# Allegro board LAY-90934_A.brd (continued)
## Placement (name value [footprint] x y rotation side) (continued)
R358  $  [0402_CC]  139.45 16.51 270 top
R359  $  [0402_CC]  34.67 16 0 top
R360  $  [0402_CC]  44.2 15.75 0 top
R361  $  [1206_CC]  79.25 15.62 270 top
R362  $  [0402_CC]  34.67 14.99 0 top
R363  $  [0402_CC]  67.94 14.35 180 top
R364  $  [0402_CC]  34.67 13.97 0 top
R365  $  [1206_CC]  52.07 13.34 180 top
R366  $  [0402_CC]  67.94 13.34 180 top
R367  $  [0402_CC]  20.7 12.95 90 top
R368  $  [0402_CC]  34.67 12.95 0 top
R369  $  [0402_CC]  29.97 11.94 270 top
R370  $  [0402_CC]  30.99 11.94 270 top
R371  $  [0402_CC]  2.29 11.81 270 top
R372  $  [0402_CC]  79.63 11.3 270 top
R373  $  [0402_CC]  64.77 10.54 90 top
R374  $  [0402_CC]  65.79 10.54 90 top
R375  $  [0402_CC]  70.1 10.54 270 top
R376  $  [0402_CC]  71.12 10.54 270 top
R377  $  [RC0402_25]  13.08 9.27 90 top
R378  $  [RC0402_25]  19.81 9.27 90 top
R379  $  [0402_CC]  1.52 6.48 90 top
R380  $  [0402_CC]  68.2 6.22 90 top
R381  $  [0402_CC]  75.18 6.22 90 top
R382  $  [0402_CC]  64.77 5.08 270 top
R383  $  [0402_CC]  75.18 4.57 90 top
R384  $  [0402_CC]  79.38 4.32 270 top
R385  $  [0402_CC]  68.2 3.81 270 top
R386  10K  [0402_CC]  135.64 2.92 90 top
R387  10K  [0402_CC]  136.91 2.92 90 top
R388  $  [RC0402_25]  77.98 80.65 270 bottom
R389  $  [RC0402_25]  75.18 80.65 270 bottom
R390  $  [RC0402_25]  72.39 80.65 270 bottom
R391  $  [0402_CC]  79.63 75.31 90 bottom
R392  10K  [0402_CC]  78.61 75.31 270 bottom
R393  $  [0402_CC]  76.83 75.31 90 bottom
R394  10K  [0402_CC]  75.82 75.31 270 bottom
R395  $  [0402_CC]  73.91 75.31 90 bottom
R396  10K  [0402_CC]  72.9 75.31 270 bottom
R397  $  [0402_CC]  49.02 73.53 90 bottom
R398  $  [0402_CC]  48.01 73.53 90 bottom
R399  $  [0402_CC]  46.99 73.53 90 bottom
R400  $  [0402_CC]  58.42 73.03 90 bottom
R401  $  [0402_CC]  57.4 73.03 90 bottom
R402  $  [0402_CC]  56.39 73.03 90 bottom
R403  $  [0402_CC]  55.37 73.03 90 bottom
R404  $  [0402_CC]  115.19 72.52 0 bottom
R405  4.7K  [0402_CC]  103.89 68.58 90 bottom
R406  $  [RC0402_25]  102.87 68.58 270 bottom
R407  $  [RC0402_25]  101.85 68.58 270 bottom
R408  4.7K  [0402_CC]  100.84 68.58 90 bottom
R409  $  [0402_CC]  58.42 67.06 90 bottom
R410  $  [0402_CC]  57.4 67.06 90 bottom
R411  $  [0402_CC]  56.39 67.06 270 bottom
R412  $  [0402_CC]  55.37 67.06 270 bottom
R413  10K  [0402_CC]  51.56 66.42 90 bottom
R414  10K  [0402_CC]  50.55 66.42 90 bottom
R415  10K  [0402_CC]  52.58 66.42 90 bottom
R416  $  [0402_CC]  49.28 66.42 270 bottom
R417  $  [0402_CC]  48.26 66.42 270 bottom
R418  $  [0402_CC]  47.24 66.42 270 bottom
R419  $  [RC0402_25]  102.87 66.04 90 bottom
R420  $  [RC0402_25]  101.85 66.04 90 bottom
R421  $  [0402_CC]  67.82 65.53 90 bottom
R422  $  [0402_CC]  66.55 65.53 90 bottom
R423  $  [0402_CC]  65.28 65.53 90 bottom
R424  $  [0402_CC]  64.01 65.53 90 bottom
R425  $  [0402_CC]  40.39 64.77 270 bottom
R426  10K  [0402_CC]  39.37 64.77 90 bottom
R427  $  [RC0402_25]  60.32 64.52 0 bottom
R428  $  [RC0402_25]  60.32 63.5 0 bottom
R429  $  [RC0402_25]  60.32 62.48 0 bottom
R430  10K  [0402_CC]  114.05 61.85 90 bottom
R431  $  [RC0402_25]  60.32 61.47 0 bottom
R432  $  [0402_CC]  60.32 60.45 180 bottom
R433  2.2K  [0402_CC]  111.38 60.2 180 bottom
R434  2.2K  [0402_CC]  111.38 58.93 180 bottom
R435  $  [0402_CC]  53.72 49.4 0 bottom
R436  $  [0402_CC]  57.15 49.15 0 bottom
R437  $  [0402_CC]  55.75 48.77 270 bottom
R438  $  [0402_CC]  59.18 41.15 270 bottom
R439  $  [0402_CC]  48.39 38.99 180 bottom
R440  $  [0402_CC]  41.66 36.7 180 bottom
R441  $  [RC0402_25]  35.94 36.7 180 bottom
R442  $  [0402_CC]  77.98 36.58 180 bottom
R443  $  [RC0402_25]  96.52 36.45 270 bottom
R444  4.7K  [RC0402_25]  95.5 36.45 270 bottom
R445  4.7K  [RC0402_25]  94.49 36.45 270 bottom
R446  4.7K  [RC0402_25]  93.47 36.45 270 bottom
R447  4.7K  [RC0402_25]  92.46 36.45 270 bottom
R448  $  [0402_CC]  41.66 35.69 180 bottom
R449  $  [0201_CC]  32.77 35.18 180 bottom
R450  $  [0402_CC]  41.66 34.67 180 bottom
R451  $  [0201_CC]  32.77 34.42 180 bottom
R452  4.7K  [RC0402_25]  96.52 33.91 270 bottom
R453  $  [RC0402_25]  95.5 33.91 270 bottom
R454  $  [RC0402_25]  94.49 33.91 270 bottom
R455  $  [RC0402_25]  93.47 33.91 270 bottom
R456  $  [RC0402_25]  92.46 33.91 270 bottom
R457  $  [RC0402_25]  91.44 33.91 270 bottom
R458  0  [0402_CC]  90.42 33.91 270 bottom
R459  $  [0402_CC]  41.66 33.66 180 bottom
R460  $  [0402_CC]  41.66 32.64 180 bottom
R461  $  [0402_CC]  41.66 31.62 180 bottom
R462  $  [0603_CC]  95.38 31.5 90 bottom
R463  $  [0402_CC]  33.27 31.24 270 bottom
R464  10K  [0402_CC]  32.26 31.24 270 bottom
R465  $  [0402_CC]  124.97 31.12 0 bottom
R466  $  [0402_CC]  41.66 30.61 180 bottom
R467  $  [0402_CC]  124.97 30.1 0 bottom
R468  $  [0603_CC]  87.12 30.1 270 bottom
R469  $  [0402_CC]  41.66 29.59 180 bottom
R470  $  [0402_CC]  34.92 29.59 180 bottom
R471  1.5K  [0402_CC]  97.92 29.08 180 bottom
R472  0  [0402_CC]  47.12 22.48 270 bottom
R473  $  [0402_CC]  46.74 20.7 0 bottom
R474  $  [RC0402_25]  45.34 20.19 270 bottom
R475  $  [0402_CC]  21.97 16.38 90 bottom
R476  1K  [0402_CC]  53.09 7.11 0 bottom
R477  $  [0402_CC]  53.09 6.1 0 bottom
R478  $  [0402_CC]  53.09 4.83 180 bottom
R479  $  [RC0805_OV]  54.99 3.3 180 bottom
R480  0  [0402_CC]  125.73 16.51 90 top
R481  $  [0402_CC]  33.27 31.24 270 top
S1  $  [SW_2P8X5P7_SM]  34.29 67.18 270 top
SW1  $  [SW4_SKRP]  14.73 80.77 0 top
SW2  $  [SW4_SKRP]  25.53 80.77 0 top
SW3  $  [SW_CHS_04_A]  65.91 68.2 90 top
SW4  $  [SW_CHS_04_A]  133.73 67.18 0 top
SW5  $  [SW6_DPDT_M096H_TH]  73.41 1.65 180 top
TP1  TP_35MIL  [TESTPOINT_35MIL]  78.11 83.19 0 top
TP2  TP_35MIL  [TESTPOINT_35MIL]  8.08 82.07 0 top
TP3  -  [TPAD_050]  39.32 33.02 0 top
TP4  TP_35MIL  [TESTPOINT_35MIL]  25.27 78.11 0 top
TP5  TP_35MIL  [TESTPOINT_35MIL]  29.08 78.11 0 top
TP6  TP_35MIL  [TESTPOINT_35MIL]  11.18 76.96 0 top
TP7  -  [TPAD_020]  19.05 74.8 90 top
TP8  -  [TPAD_020]  20.32 74.8 90 top
TP9  -  [TPAD_020]  17.78 73.28 90 top
TP10  -  [TPAD_020]  19.05 73.28 90 top
TP11  -  [TPAD_020]  20.32 73.28 90 top
TP12  -  [TPAD_050]  82.68 73.28 0 top
TP13  -  [TPAD_020]  43.18 73.15 0 top
TP14  -  [TPAD_020]  101.73 71.88 0 top
TP15  -  [TPAD_020]  47.5 69.09 0 top
TP16  TP_35MIL  [TESTPOINT_35MIL]  101.85 68.96 0 top
TP17  TP_35MIL  [TESTPOINT_35MIL]  103.25 68.96 0 top
TP18  -  [TPAD_020]  47.5 67.82 0 top
TP19  -  [TPAD_020]  86.49 68.2 0 top
TP20  -  [TPAD_020]  87.76 68.2 0 top
TP21  -  [TPAD_020]  90.55 68.2 0 top
TP22  -  [TPAD_020]  92.46 68.2 0 top
TP23  -  [TPAD_020]  93.73 68.2 0 top
TP24  -  [TPAD_020]  20.7 67.18 90 top
TP25  -  [TPAD_020]  20.68 65.91 90 top
TP26  -  [TPAD_020]  85.22 64.9 0 top
TP27  -  [TPAD_020]  86.49 64.9 0 top
TP28  -  [TPAD_050]  14.73 59.28 0 top
TP29  TP_35MIL  [TESTPOINT_35MIL]  69.09 62.87 90 top
TP30  -  [TPAD_015]  91.31 62.23 0 top
TP31  -  [TPAD_015]  95.12 62.23 0 top
TP32  TP_35MIL  [TESTPOINT_35MIL]  69.09 61.47 90 top
TP33  TP_35MIL  [TESTPOINT_35MIL]  64.64 61.21 90 top
TP34  TP_35MIL  [TESTPOINT_35MIL]  66.04 61.21 90 top
TP35  -  [TPAD_015]  79.5 58.55 0 top
TP36  -  [TPAD_015]  82.8 57.17 0 top
TP37  TP_35MIL  [TESTPOINT_35MIL]  16 56.9 270 top
TP38  TP_35MIL  [TESTPOINT_35MIL]  17.4 56.9 270 top
TP39  -  [TPAD_015]  84.84 55.63 0 top
TP40  -  [TPAD_050]  108.97 55.63 0 top
TP41  TP_35MIL  [TESTPOINT_35MIL]  49.15 55.37 0 top
TP42  TP_35MIL  [TESTPOINT_35MIL]  50.55 55.12 0 top
TP43  -  [TPAD_015]  85.72 55.12 0 top
TP44  -  [TPAD_020]  125.6 55.12 0 top
TP45  -  [TPAD_015]  84.84 54.99 0 top
TP46  -  [TPAD_020]  13.84 54.61 270 top
TP47  -  [TPAD_015]  85.06 54.36 0 top
TP48  -  [TPAD_015]  85.09 53.72 0 top
TP49  -  [TPAD_015]  85.47 53.09 0 top
TP50  -  [TPAD_020]  125.6 52.83 0 top
TP51  -  [TPAD_015]  84.84 52.71 0 top
TP52  TP_35MIL  [TESTPOINT_35MIL]  57.4 52.45 90 top
TP53  TP_35MIL  [TESTPOINT_35MIL]  62.48 52.45 90 top
TP54  -  [TPAD_015]  85.47 52.07 0 top
TP55  -  [TPAD_020]  125.73 51.69 0 top
TP56  TP_35MIL  [TESTPOINT_35MIL]  37.08 51.44 180 top
TP57  TP_35MIL  [TESTPOINT_35MIL]  40.77 51.44 0 top
TP58  TP_35MIL  [TESTPOINT_35MIL]  42.29 51.44 0 top
TP59  TP_35MIL  [TESTPOINT_35MIL]  44.58 51.44 180 top
TP60  -  [TPAD_015]  85.6 51.44 0 top
TP61  TP_35MIL  [TESTPOINT_35MIL]  122.43 51.44 90 top
TP62  TP_35MIL  [TESTPOINT_35MIL]  123.83 51.44 90 top
TP63  TP_35MIL  [TESTPOINT_35MIL]  62.48 50.93 90 top
TP64  -  [TPAD_015]  85.6 50.8 0 top
TP65  -  [TPAD_015]  84.84 50.67 0 top
TP66  TP_35MIL  [TESTPOINT_35MIL]  45.21 50.17 180 top
TP67  -  [TPAD_015]  85.09 49.91 0 top
TP68  TP_35MIL  [TESTPOINT_35MIL]  33.4 49.66 180 top
TP69  TP_35MIL  [TESTPOINT_35MIL]  34.92 49.66 180 top
TP70  TP_35MIL  [TESTPOINT_35MIL]  37.08 49.66 180 top
TP71  -  [TPAD_020]  54.15 48.51 90 top
TP72  -  [TPAD_015]  84.96 49.15 0 top
TP73  -  [TPAD_015]  84.84 47.31 0 top
TP74  TP_35MIL  [TESTPOINT_35MIL]  58.55 47.12 180 top
TP75  -  [TPAD_050]  60.71 47.12 0 top
TP76  TP_35MIL  [TESTPOINT_35MIL]  37.85 46.99 180 top
TP77  -  [TPAD_015]  84.96 46.61 0 top
TP78  -  [TPAD_015]  81.51 48.11 180 bottom
TP79  -  [TPAD_015]  80.86 48.11 180 bottom
TP80  TP_35MIL  [TESTPOINT_35MIL]  35.81 45.21 0 top
TP81  TP_35MIL  [TESTPOINT_35MIL]  37.85 45.21 0 top
TP82  TP_35MIL  [TESTPOINT_35MIL]  129.03 44.96 0 top
TP83  -  [TPAD_020]  91.82 44.58 0 top
TP84  -  [TPAD_020]  90.55 44.32 0 top
TP85  -  [TPAD_020]  58.42 44.2 270 top
TP86  -  [TPAD_020]  86.23 43.18 0 top
TP87  -  [TPAD_020]  87.5 43.18 0 top
TP88  -  [TPAD_020]  88.77 43.18 0 top
TP89  -  [TPAD_020]  91.06 43.18 0 top
TP90  -  [TPAD_020]  104.77 42.93 0 top
TP91  TP_35MIL  [TESTPOINT_35MIL]  35.81 41.66 90 top
TP92  TP_35MIL  [TESTPOINT_35MIL]  37.85 41.66 180 top
TP93  -  [TPAD_020]  97.03 42.8 0 top
TP94  TP_35MIL  [TESTPOINT_35MIL]  138.81 41.66 0 top
TP95  -  [TPAD_020]  86.23 41.28 0 top
TP96  -  [TPAD_020]  87.5 41.28 0 top
TP97  -  [TPAD_020]  7.24 40.77 0 top
TP98  TP_35MIL  [TESTPOINT_35MIL]  121.28 40.51 90 top
TP99  -  [TPAD_020]  14.22 40.39 0 top
TP100  -  [TPAD_020]  15.49 40.39 0 top
TP101  -  [TPAD_020]  16.76 40.39 0 top
TP102  TP_35MIL  [TESTPOINT_35MIL]  56.26 40.39 180 top
TP103  -  [TPAD_015]  104.77 40.39 0 top
TP104  -  [TPAD_020]  89.92 40.26 0 top
TP105  TP_35MIL  [TESTPOINT_35MIL]  39.62 40.01 180 top
TP106  TP_35MIL  [TESTPOINT_35MIL]  64.52 39.88 0 top
TP107  -  [TPAD_020]  104.77 39.12 0 top
TP108  TP_35MIL  [TESTPOINT_35MIL]  35.81 38.1 0 top
TP109  TP_35MIL  [TESTPOINT_35MIL]  37.97 38.1 0 top
TP110  -  [TPAD_020]  104.77 37.85 0 top
TP111  TP_35MIL  [TESTPOINT_35MIL]  49.02 37.47 180 top
TP112  TP_35MIL  [TESTPOINT_35MIL]  51.43 37.47 180 top
TP113  TP_35MIL  [TESTPOINT_35MIL]  52.83 37.47 180 top
TP114  -  [TPAD_020]  18.67 36.83 0 top
TP115  TP_35MIL  [TESTPOINT_35MIL]  3.17 36.7 0 top
TP116  TP_35MIL  [TESTPOINT_35MIL]  60.58 36.07 0 top
TP117  TP_35MIL  [TESTPOINT_35MIL]  62.86 36.07 0 top
TP118  TP_35MIL  [TESTPOINT_35MIL]  45.72 35.81 180 top
TP119  TP_35MIL  [TESTPOINT_35MIL]  47.62 35.81 180 top
TP120  TP_35MIL  [TESTPOINT_35MIL]  49.15 35.81 180 top
TP121  TP_35MIL  [TESTPOINT_35MIL]  54.23 35.81 270 top
TP122  -  [TPAD_020]  18.67 35.56 0 top
TP123  -  [TPAD_020]  3.17 35.05 0 top
TP124  TP_35MIL  [TESTPOINT_35MIL]  26.92 34.54 90 top
TP126  TP_35MIL  [TESTPOINT_35MIL]  54.23 34.29 270 top
TP127  TP_35MIL  [TESTPOINT_35MIL]  49.15 34.16 180 top
TP128  -  [TPAD_050]  142.11 33.78 0 top
TP130  TP_35MIL  [TESTPOINT_35MIL]  30.1 32.13 0 top
TP131  TP_35MIL  [TESTPOINT_35MIL]  64.9 32.13 0 top
TP132  TP_35MIL  [TESTPOINT_35MIL]  66.93 32.13 0 top
TP133  -  [TPAD_020]  95.12 32 0 top
TP134  -  [TPAD_020]  96.39 32 0 top
TP135  TP_35MIL  [TESTPOINT_35MIL]  97.16 30.86 0 top
TP136  -  [TPAD_020]  3.17 30.73 0 top
TP137  -  [TPAD_020]  95.12 30.73 0 top
TP138  -  [TPAD_020]  86.87 30.48 0 top
TP139  TP_35MIL  [TESTPOINT_35MIL]  30.1 30.1 0 top
TP140  -  [TPAD_020]  97.16 29.08 0 top
TP141  TP_35MIL  [TESTPOINT_35MIL]  133.1 29.08 0 top
TP142  -  [TPAD_020]  142.11 28.7 90 top
TP143  -  [TPAD_020]  97.79 28.07 0 top
TP144  -  [TPAD_020]  97.79 26.8 0 top
TP145  TP_35MIL  [TESTPOINT_35MIL]  24.51 25.91 90 top
TP146  -  [TPAD_020]  101.35 25.65 0 top
TP147  -  [TPAD_020]  2.92 24.77 270 top
TP148  -  [TPAD_020]  101.35 24.38 0 top
TP149  -  [TPAD_020]  115.25 24.26 0 top
TP150  -  [TPAD_020]  115.25 22.99 0 top
TP151  -  [TPAD_020]  45.21 18.03 90 top
TP152  -  [TPAD_050]  66.07 17.25 0 top
TP153  -  [TPAD_020]  67.94 17.15 0 top
TP154  -  [TPAD_020]  33.66 17.02 0 top
TP156  -  [TPAD_020]  67.94 15.49 0 top
TP157  -  [TPAD_020]  74.55 15.49 0 top
TP158  -  [TPAD_020]  2.92 15.37 270 top
TP159  -  [TPAD_020]  4.19 15.37 270 top
TP160  TP_35MIL  [TESTPOINT_35MIL]  5.84 15.37 0 top
TP161  TP_35MIL  [TESTPOINT_35MIL]  8 15.37 0 top
TP162  TP_35MIL  [TESTPOINT_35MIL]  104.01 14.48 0 top
TP163  TP_35MIL  [TESTPOINT_35MIL]  112.9 14.48 0 top
TP164  TP_35MIL  [TESTPOINT_35MIL]  66.04 14.35 0 top
TP165  -  [TPAD_020]  74.55 14.22 0 top
TP166  -  [TPAD_020]  28.19 13.97 270 top
TP167  -  [TPAD_050]  15.75 12.95 0 top
TP168  TP_35MIL  [TESTPOINT_35MIL]  66.04 12.95 0 top
TP169  -  [TPAD_020]  67.31 12.19 0 top
TP170  -  [TPAD_020]  68.71 12.19 0 top
TP171  -  [TPAD_020]  33.66 11.94 0 top
TP172  -  [TPAD_020]  74.17 10.54 0 top
TP173  -  [TPAD_020]  28.57 9.27 0 top
TP174  -  [TPAD_020]  32.38 9.27 0 top
TP175  -  [TPAD_020]  48.26 8.64 0 top
TP176  -  [TPAD_020]  49.53 8.64 0 top
TP177  -  [TPAD_020]  125.6 4.45 0 top
TP178  -  [TPAD_020]  132.21 4.45 0 top
TP179  -  [TPAD_020]  133.48 4.45 0 top
TP180  -  [TPAD_020]  135.64 4.45 0 top
TP181  -  [TPAD_020]  136.91 4.45 0 top
TP182  -  [TPAD_020]  139.45 4.45 0 top
TP183  -  [TPAD_020]  138.18 2.92 0 top
TP184  -  [TPAD_020]  139.45 2.92 0 top
TP185  -  [TPAD_050]  57.78 2.79 270 top
TP186  TP_35MIL  [TESTPOINT_35MIL]  59.36 74.12 90 top
TP187  TP_35MIL  [TESTPOINT_35MIL]  59.36 72.39 90 top
TP188  -  [TPAD_050]  57.78 6.35 0 top
TVS1  $  [DIODE2_SOD523]  110.74 14.48 0 top
TVS2  $  [DIODE2_SOD523]  106.17 14.48 180 top
TVS3  $  [DIODE2_SOD523]  11.94 9.4 270 top
U1  $  [PBGA208_0P5_9X9MM_SM]  94.23 52.83 0 top
U2  $  [BGA200_0P65X0P8_10P1X14P6]  76.96 51.31 270 top
U3  $  [SC70-5]  8 79.88 270 top
U4  $  [LGA8_3P1X4P1MM_SPK0641]  4.06 78.87 0 top
U5  $  [LGA8_3P1X4P1MM_SPK0641]  80.64 78.87 0 top
U6  $  [WLCSP6_0P5_0P89X1P39]  87.88 75.95 180 top
U7  $  [SOT-23-5]  8 74.3 270 top
U8  $  [SO8_1P27_4X5]  27.18 71.63 270 top
U9  TMUX1574RSVR  [PQFN16_0P4_2P65X1P85]  116.08 71.37 0 top
U10  $  [PQFN16_0P4_2P65X1P85]  99.06 70.99 0 top
U11  $  [WLCSP6_0P4_0P84X1P18]  102.23 70.49 270 top
U12  $  [SO16_0P5_3P5X4P5_MM]  17.53 70.23 90 top
U13  $  [QFN24_4X4_EP2P25MM]  43.94 69.85 0 top
U14  74AUP1G126GM  [UDFN6_1X1P5MM]  40 64.77 270 top
U15  $  [UQFN32_0P5_5X5_EP3X3]  116.71 62.48 90 top
U16  $  [QFN16_0P65_4X4_A]  46.23 58.29 0 top
U17  $  [QFN16_0P65_4X4_A]  28.57 54.99 0 top
U18  $  [HWSON8_0P5_3P1X2P1]  15.75 52.07 270 top
U19  $  [WSON10_0P5_2P1X3P1]  56.52 49.66 0 top
U20  $  [WSON8_1P27_8X6MM_EP136X171]  121.92 46.1 90 top
U21  $  [QFN16_0P65_4X4_A]  20.07 45.34 0 top
U22  $  [SOT753_5P_1P7X3P1MM]  136.27 44.45 0 top
U23  $  [QFN40_0P4_5X5_EP146X146]  48.39 44.07 180 top
U24  $  [WSON10_0P5_2P1X3P1]  59.69 41.78 270 top
U25  $  [FBGA153_0P5_11P5X13]  111.51 41.28 0 top
U26  $  [WLCSP4_0P5_0P99X0P99]  136.27 39.37 270 top
U27  $  [PQFN16_0P4_2P65X1P85]  81.28 35.43 0 top
U28  $  [LQFP64_0P5_10X10]  11.05 32.77 90 top
U29  TMUX1574RSVR  [PQFN16_0P4_2P65X1P85]  112.52 32.13 90 top
U30  TMUX1574RSVR  [PQFN16_0P4_2P65X1P85]  116.97 32.13 90 top
U31  $  [PQFN16_0P4_2P65X1P85]  127.38 32.13 90 top
U32  $  [QFN12_0P5_2X3MM_EP]  139.95 30.23 0 top
U33  $  [SOT23-5]  23.5 30.1 0 top
U34  $  [SC70-5]  72.64 29.97 0 top
U35  $  [QFN40_0P4_5X5MM]  91.06 29.34 90 top
U36  $  [SOT-23-5]  30.99 24 270 top
U37  $  [XSON10_0P5_1P1X2P6MM]  88.52 22.35 90 top
U38  $  [XSON10_0P5_1P1X2P6MM]  93.6 22.35 90 top
U39  $  [QFN0505-32B_0P5]  48.01 22.1 90 top
U40  $  [TSSOP16]  108.46 21.59 180 top
U41  $  [UQFN12_1P7X2MM]  122.43 21.21 90 top
U42  $  [SOT23-6]  4.06 20.45 180 top
U43  $  [XQFN12_0P4_1P8X2P1]  129.79 19.69 90 top
U44  $  [XQFN12_0P4_1P8X2P1]  138.43 19.69 90 top
U45  $  [WLCSP15_0P5_1P57X2P59]  66.29 19.43 270 top
U46  $  [SOT-23]  26.42 17.4 90 top
U47  $  [WLCSP42_0P4_2P94X2P54_SMDP]  19.3 16.26 180 top
U48  $  [HX2QFN16_0P4_2P7X2P7]  31.5 15.24 90 top
U49  $  [HX2QFN16_0P4_2P7X2P7]  71.25 13.84 270 top
U50  $  [SOT23-5]  8.13 12.6 90 top
U51  $  [WLCSP12_0P4_1P3X1P7MM_SMDP]  27.69 11.94 90 top
U52  $  [WLCSP12_0P4_1P3X1P7MM_SMDP]  75.69 10.29 180 top
U53  $  [SC70-5]  8.13 9.4 270 top
U54  $  [WLCSP5_0P4_0P82X1P22]  14.48 9.27 180 top
U55  $  [WLCSP5_0P4_0P82X1P22]  29.85 9.27 180 top
U56  $  [LGA8_3P1X4P1MM_SPK0641]  4.06 8 0 top
U57  $  [LGA8_3P1X4P1MM_SPK0641]  80.64 8 0 top
U58  $  [DFN2020_0P5_SQ2]  54.99 5.97 270 top
U59  TMUX1574RSVR  [PQFN16_0P4_2P65X1P85]  128.78 70.61 0 bottom
U60  $  [XQFN16_0P4_2P7X1P9]  57.66 69.98 90 bottom
U61  $  [SSOP8_DCU]  51.31 69.98 180 bottom
U62  $  [SSOP8_DCU]  48.26 69.98 0 bottom
U63  $  [XQFN16_0P4_2P7X1P9]  63.25 62.74 180 bottom
U64  $  [QFN16_0P65_4X4_A]  36.83 33.15 0 bottom
U65  $  [XQFN12_0P4_1P8X2P1]  20.96 29.97 0 bottom
U66  $  [SC70-5]  80.64 83.19 270 top
U67  $  [WLCSP6_0P5_0P89X1P39]  87.63 82.04 180 top
U68  $  [SC70-5]  132.21 47.75 90 bottom
X1  $  [XTAL_4_3P3X2P6MM]  9.02 22.1 0 top
Y1  $  [XTLOSC4_3P2X2P5MM_SM]  95.76 65.79 180 top
Y2  $  [XTL4_2P5X2MM_SM]  83.31 30.61 0 top

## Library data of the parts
BH1-BH5 = MOUNT_HOLE
BT1 = BATTERY_SKT_3V
C1-C9 C11-C13 C15-C28 C30-C33 C36 C38-C49 C51 C53-C63 C66-C70 C72-C93 C96-C111 C113 C115-C119 C122-C125 C127 C129-C133 C135-C140 C142-C146 C149-C153 C155-C176 C178-C196 C198 C200-C223 C225 C226 C228 C229 C231 C232 C234 C235 C237-C242 C244-C261 C263-C268 C270-C275 C277-C279 C281-C283 C286-C288 C290-C296 C298 C299 C301-C318 = CAP_NP
C10 C14 C29 C34 C35 C37 C50 C52 C64 C65 C71 C114 C120 C148 C177 C197 C199 C224 C227 C230 C233 C236 C243 C269 C276 C280 C284 C285 C289 C297 C300 = CAP_NP: tolerance: 10%
C94 C95 C112 C121 C262 = CAP_NP: room: RGMII_PHY
C128 C134 = CAP_NP: tolerance: 5%; room: RGMII_PHY
C141 = CAP_POL
C154 = MOT_CAP
D1 = LED_GPLY6900
D2 = ESD_DIODE_2LINE
D3 D18-D20 D22-D25 D30 = DIODE_SCHTKY
D5 D15-D17 D26-D28 = LED
D6 D7 D9 D11-D13 = DIODE_BIDIR
D10 D14 TVS1-TVS3 = DIODE_TVS_BIDIR
D29 = ZDIODE
F1 F2 = FUSE
GND1 GND2 GND7 GND17 GND26 GND27 TP1 TP2 TP4-TP6 TP16 TP17 TP29 TP32-TP34 TP37 TP38 TP41 TP42 TP52 TP53 TP56-TP59 TP61-TP63 TP66 TP68-TP70 TP74 TP76 TP80-TP82 TP91 TP92 TP94 TP98 TP102 TP105 TP106 TP108 TP109 TP111-TP113 TP115-TP121 TP124 TP126 TP127 TP130-TP132 TP135 TP139 TP141 TP145 TP160-TP164 TP168 TP186 TP187 = T POINT R: Tolerance: TOLERANCE; User Part Number: 510-75618
GND3-GND6 GND8-GND13 GND15 GND16 GND18-GND21 GND23 GND24 GND28 TP3 TP7-TP15 TP18-TP28 TP30 TP31 TP35 TP36 TP39 TP40 TP43-TP51 TP54 TP55 TP60 TP64 TP65 TP67 TP71-TP73 TP75 TP77-TP79 TP83-TP90 TP93 TP95-TP97 TP99-TP101 TP103 TP104 TP107 TP110 TP114 TP122 TP123 TP128 TP133 TP134 TP136-TP138 TP140 TP142-TP144 TP146-TP154 TP156-TP159 TP165-TP167 TP169-TP185 TP188 = TESTLOOP
GND14 GND22 GND25 = TestLoop
J1 = CONN_HDR_3X2
J2 = CONN_HDR_4X1
J3 J5 = CONN_HDR_4X2
J4 = CONN_HDR_20X2
J6 = CONN_MICRO_SDCARD
J7 = CONN_HDR_5X2
J8 = CON_67_FEMALE_RA_B
J9 = RJ45_2 DUAL_LED_10P
J10 = CON_KJ366EYS_AUDIOJACK_6P
J11 J12 = USB24_TYPEC_SH4
J13 = USB6_TYPEC_SH4_1_A
L1 L2 L11 L13-L18 = BEAD_0
L3 L4 = DLW43
L5 L6 L8 L9 = INDUCTOR
L7 = INDUCTOR_FERRITE
L10 = INDUCTOR: tolerance: 20%
L12 = IND
Q1 Q3-Q6 Q8-Q13 = NX3008NBKW_SOT323
QZ1 QZ2 = XTAL
R1-R99 R101-R132 R134-R146 R148-R152 R154-R157 R159-R170 R172-R176 R178-R185 R187-R261 R263-R269 R271-R274 R276-R279 R281-R283 R285-R301 R303-R470 R472-R481 = RES
R133 R147 R153 R171 R177 R186 = RES: signal model: RES_0402_CC_DISCRETE_0.45_MM_470-75394_0_0
R280 = RES: tolerance: 5%
R284 R302 = RES: tolerance: 1%
R471 = RES: room: RGMII_PHY
S1 = SW-SPST_A
SW1 SW2 = SW_TC_SPST_4P
SW3 SW4 = CHS-04TA_SW
SW5 = SW_DPDT_3
U1 = MIMX9122DVXxLAA_BGA208_A
U2 = MT53B768M32D4NQ_200P
U3 U53 U66 = 74LV1T34GWH_TSSOP6
U4 U5 U56 U57 = SPK0641HT4H_8P_A
U6 U67 = NX5P2924DUK_WLCSP6
U7 = NCP161ASN180T1G_A
U8 = TJA1057GT3_8P
U9 U29 U30 U59 = TMUX1574RSVR_A: signal model: TMUX1574RSVR_A_PQFN16_0P4_2P65X1P85_IC_0.55MM_312-82341_TMUX1574RSVR_TMUX1574RSVR
U10 U27 U31 = TMUX1574RSVR_A
U11 = P3T2108_6P
U12 = PCF2131_A
U13 = PCA9655EMTTXG_WQFN24_A
U14 = 74AUP1G126GM
U15 = PCAL6524HE_QFN
U16 U17 U21 U64 = PAC1934_UQFN16_A
U18 = PCT2075 _SON8_EP
U19 U24 = TPS22990NDMLT_WSON10_B
U20 = GD5F1GQ4RCYIG_WSON8
U22 = 74LV1T126GVH
U23 = PF9453AHN_QFN40P
U25 = SDINBDA6_32G_I_VFBGA_153P
U26 = NX3P1108_4P
U28 = FT4232HL_LQFP64
U32 = MP2147GD_QFN_11P
U33 U50 = RT9193-33PB
U34 U68 = 74AUP1G07GW
U35 = RTL8211FDI-40P
U36 = SGM8709YN5G
U37 U38 = DIODE_ESD_4CH_10P_A
U39 = R1273L031A
U40 = WM8524GEDT
U41 = LSF0204_QFN_12P
U42 = 93AA56BT_SOT23-6
U43 U44 = NTB0104GU12_12P
U45 = NX20P5090UK_15P_A
U46 = LM3480IM3
U47 = NX20P3483UK_42P
U48 U49 = PTN5110_QFN16
U51 U52 = NX20P0407_WLCSP12_A
U54 U55 = PESD1USB30_5P
U58 = DML3006LFDS-7_A
U60 U63 = 74AVC4T245GU_XQFN16
U61 = SN74AUP3G04_A
U62 = 74HC3G06DC
U65 = 74AVC4T3144_12P_A
X1 Y1 Y2 = XTAL_13

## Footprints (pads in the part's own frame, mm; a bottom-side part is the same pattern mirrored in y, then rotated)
0201_CC
  rect 0.305x0.305 smd: 1(-0.267,0) 2(0.267,0)
0402_CC
  rect 0.457x0.508 smd: 1(-0.375,0) 2(0.375,0)
0402_CC_NSP
  rect 0.457x0.508 smd: 1(-0.375,0) 2(0.375,0)
0603_CC
  rect 0.711x0.838 smd: 1(-0.65,0) 2(0.65,0)
0805_CC
  rect 0.94x1.346 smd: 1(-0.78,0) 2(0.78,0)
1206_CC
  rect 0.94x1.702 smd: 1(-1.4,0) 2(1.4,0)
1210_CC
  rect 0.94x2.591 smd: 1(-1.4,0) 2(1.4,0)
BATT_6P8MM_SM
  rect 1.778x5.08 smd: 1(-4.701,0) 2(4.701,0)
  rect 3.962x3.962 smd: 3(0,0)
BGA200_0P65X0P8_10P1X14P6
  round 0.279 smd: A1(-4.4,6.825) A2(-3.6,6.825) A3(-2.8,6.825) A4(-2,6.825) A5(-1.2,6.825) A8(1.2,6.825) A9(2,6.825) A10(2.8,6.825) A11(3.6,6.825) A12(4.4,6.825) AA1(-4.4,-6.175) AA2(-3.6,-6.175) AA3(-2.8,-6.175) AA4(-2,-6.175) AA5(-1.2,-6.175) AA8(1.2,-6.175) AA9(2,-6.175) AA10(2.8,-6.175) AA11(3.6,-6.175) AA12(4.4,-6.175) AB1(-4.4,-6.825) AB2(-3.6,-6.825) AB3(-2.8,-6.825) AB4(-2,-6.825) AB5(-1.2,-6.825) AB8(1.2,-6.825) AB9(2,-6.825) AB10(2.8,-6.825) AB11(3.6,-6.825) AB12(4.4,-6.825) B1(-4.4,6.175) B2(-3.6,6.175) B3(-2.8,6.175) B4(-2,6.175) B5(-1.2,6.175) B8(1.2,6.175) B9(2,6.175) B10(2.8,6.175) B11(3.6,6.175) B12(4.4,6.175) C1(-4.4,5.525) C2(-3.6,5.525) C3(-2.8,5.525) C4(-2,5.525) C5(-1.2,5.525) C8(1.2,5.525) C9(2,5.525) C10(2.8,5.525) C11(3.6,5.525) C12(4.4,5.525) D1(-4.4,4.875) D2(-3.6,4.875) D3(-2.8,4.875) D4(-2,4.875) D5(-1.2,4.875) D8(1.2,4.875) D9(2,4.875) D10(2.8,4.875) D11(3.6,4.875) D12(4.4,4.875) E1(-4.4,4.225) E2(-3.6,4.225) E3(-2.8,4.225) E4(-2,4.225) E5(-1.2,4.225) E8(1.2,4.225) E9(2,4.225) E10(2.8,4.225) E11(3.6,4.225) E12(4.4,4.225) F1(-4.4,3.575) F2(-3.6,3.575) F3(-2.8,3.575) F4(-2,3.575) F5(-1.2,3.575) F8(1.2,3.575) F9(2,3.575) F10(2.8,3.575) F11(3.6,3.575) F12(4.4,3.575) G1(-4.4,2.925) G2(-3.6,2.925) G3(-2.8,2.925) G4(-2,2.925) G5(-1.2,2.925) G8(1.2,2.925) G9(2,2.925) G10(2.8,2.925) G11(3.6,2.925) G12(4.4,2.925) H1(-4.4,2.275) H2(-3.6,2.275) H3(-2.8,2.275) H4(-2,2.275) H5(-1.2,2.275) H8(1.2,2.275) H9(2,2.275) H10(2.8,2.275) H11(3.6,2.275) H12(4.4,2.275) J1(-4.4,1.625) J2(-3.6,1.625) J3(-2.8,1.625) J4(-2,1.625) J5(-1.2,1.625) J8(1.2,1.625) J9(2,1.625) J10(2.8,1.625) J11(3.6,1.625) J12(4.4,1.625) K1(-4.4,0.975) K2(-3.6,0.975) K3(-2.8,0.975) K4(-2,0.975) K5(-1.2,0.975) K8(1.2,0.975) K9(2,0.975) K10(2.8,0.975) K11(3.6,0.975) K12(4.4,0.975) N1(-4.4,-0.975) N2(-3.6,-0.975) N3(-2.8,-0.975) N4(-2,-0.975) N5(-1.2,-0.975) N8(1.2,-0.975) N9(2,-0.975) N10(2.8,-0.975) N11(3.6,-0.975) N12(4.4,-0.975) P1(-4.4,-1.625) P2(-3.6,-1.625) P3(-2.8,-1.625) P4(-2,-1.625) P5(-1.2,-1.625) P8(1.2,-1.625) P9(2,-1.625) P10(2.8,-1.625) P11(3.6,-1.625) P12(4.4,-1.625) R1(-4.4,-2.275) R2(-3.6,-2.275) R3(-2.8,-2.275) R4(-2,-2.275) R5(-1.2,-2.275) R8(1.2,-2.275) R9(2,-2.275) R10(2.8,-2.275) R11(3.6,-2.275) R12(4.4,-2.275) T1(-4.4,-2.925) T2(-3.6,-2.925) T3(-2.8,-2.925) T4(-2,-2.925) T5(-1.2,-2.925) T8(1.2,-2.925) T9(2,-2.925) T10(2.8,-2.925) T11(3.6,-2.925) T12(4.4,-2.925) U1(-4.4,-3.575) U2(-3.6,-3.575) U3(-2.8,-3.575) U4(-2,-3.575) U5(-1.2,-3.575) U8(1.2,-3.575) U9(2,-3.575) U10(2.8,-3.575) U11(3.6,-3.575) U12(4.4,-3.575) V1(-4.4,-4.225) V2(-3.6,-4.225) V3(-2.8,-4.225) V4(-2,-4.225) V5(-1.2,-4.225) V8(1.2,-4.225) V9(2,-4.225) V10(2.8,-4.225) V11(3.6,-4.225) V12(4.4,-4.225) W1(-4.4,-4.875) W2(-3.6,-4.875) W3(-2.8,-4.875) W4(-2,-4.875) W5(-1.2,-4.875) W8(1.2,-4.875) W9(2,-4.875) W10(2.8,-4.875) W11(3.6,-4.875) W12(4.4,-4.875) Y1(-4.4,-5.525) Y2(-3.6,-5.525) Y3(-2.8,-5.525) Y4(-2,-5.525) Y5(-1.2,-5.525) Y8(1.2,-5.525) Y9(2,-5.525) Y10(2.8,-5.525) Y11(3.6,-5.525) Y12(4.4,-5.525)
CASE_D_AL
  rect 3.556x1.575 smd: 1(-2.642,0) 2(2.642,0)
CC0402_25
  round 0.635 smd: 1(-0.508,0) 2(0.508,0)
CC0402_TOL0P15
  rect 0.457x0.61 smd: 1(-0.475,0) 2(0.475,0)
CC0603
  rect 0.991x0.813 smd: 1(-0.686,0) 2(0.686,0)
CC0603_OV
  oval 0.889x1.143 smd: 1(-0.762,0) 2(0.762,0)
CC0805_OV
  oval 0.889x1.524 smd: 1(-0.965,0) 2(0.965,0)
CC1210
  rect 1.778x2.845 smd: 1(-1.397,0) 2(1.397,0)
CON1X4_2MM_TH_303H
  rect 1.448x1.448 hole 0.813: 1(0,0)
  round 1.448 hole 0.813: 2(-2,0) 3(-4,0) 4(-6,0)
CON6_AUDIOJACK_RA_TH
  round 0 hole 1.499 unplated: (0.4,2.7) (7.4,2.7)
  oval 2.108x1.092 hole 1.499x0.508: 1(0,0) 2(0,5.15)
  rect 1.6x1.803 smd: 3(9.4,-0.8) 4(9.4,6.2) 5(6.2,6.2) 6(6.2,-0.8)
CON9_SDCARD_1P1MM
  round 0 hole 0.991 unplated: (-4.95,-3.25) (3.05,-3.25)
  rect 0.711x1.6 smd: 1(2.25,7.25) 2(1.15,7.25) 3(0.05,7.25) 4(-1.05,7.25) 5(-2.15,7.25) 6(-3.25,7.25) 7(-4.35,7.25) 8(-5.45,7.25) 9(-6.55,7.25)
  rect 1.194x1.6 smd: 10(-7.75,6.65)
  rect 1.194x2.21 smd: 11(-7.75,-2.85) 12(7.75,-2.85)
  rect 1.6x1.397 smd: 13(6.85,6.75)
CON24_USB_TYPEC_RA_SMT_TH_2P2L
  round 0 hole 0.66 unplated: (-6.775,-0.7) (0.675,-0.7)
  rect 0.305x0.711 smd: A1(-5.8,1.11) A2(-5.3,1.11) A3(-4.8,1.11) A4(-4.3,1.11) A5(-3.8,1.11) A6(-3.3,1.11) A7(-2.8,1.11) A8(-2.3,1.11) A9(-1.8,1.11) A10(-1.3,1.11) A11(-0.8,1.11) A12(-0.3,1.11)
  round 0.66 hole 0.406: B1(0,0) B2(-0.65,-0.7) B3(-1.45,-0.7) B4(-1.85,0) B5(-2.25,-0.7) B6(-2.65,0) B7(-3.45,0) B8(-3.85,-0.7) B9(-4.25,0) B10(-4.65,-0.7) B11(-5.45,-0.7) B12(-6.1,0)
  oval 1.016x1.6 hole 0.508x1.118: SH1(-7.55,0.81) SH2(1.45,0.81)
  oval 1.016x1.803 hole 0.508x1.295: SH3(-7.55,-4.8) SH4(1.45,-4.8)
CON67_0P5_TYPE-E_22X7P3_RA_270H
  rect 1.194x2.743 smd: (-10.35,2.975) (10.35,2.975)
  round 0 hole 1.1 unplated: (-10,-1.525)
  round 0 hole 1.6 unplated: (10,-1.525)
  rect 0.305x1.549 smd: 1(-9.25,3.775) 2(-9,-3.775) 3(-8.75,3.775) 4(-8.5,-3.775) 5(-8.25,3.775) 6(-8,-3.775) 7(-7.75,3.775) 8(-7.5,-3.775) 9(-7.25,3.775) 10(-7,-3.775) 11(-6.75,3.775) 12(-6.5,-3.775) 13(-6.25,3.775) 14(-6,-3.775) 15(-5.75,3.775) 16(-5.5,-3.775) 17(-5.25,3.775) 18(-5,-3.775) 19(-4.75,3.775) 20(-4.5,-3.775) 21(-4.25,3.775) 22(-4,-3.775) 23(-3.75,3.775) 32(-1.5,-3.775) 33(-1.25,3.775) 34(-1,-3.775) 35(-0.75,3.775) 36(-0.5,-3.775) 37(-0.25,3.775) 38(0,-3.775) 39(0.25,3.775) 40(0.5,-3.775) 41(0.75,3.775) 42(1,-3.775) 43(1.25,3.775) 44(1.5,-3.775) 45(1.75,3.775) 46(2,-3.775) 47(2.25,3.775) 48(2.5,-3.775) 49(2.75,3.775) 50(3,-3.775) 51(3.25,3.775) 52(3.5,-3.775) 53(3.75,3.775) 54(4,-3.775) 55(4.25,3.775) 56(4.5,-3.775) 57(4.75,3.775) 58(5,-3.775) 59(5.25,3.775) 60(5.5,-3.775) 61(5.75,3.775) 62(6,-3.775) 63(6.25,3.775) 64(6.5,-3.775) 65(6.75,3.775) 66(7,-3.775) 67(7.25,3.775) 68(7.5,-3.775) 69(7.75,3.775) 70(8,-3.775) 71(8.25,3.775) 72(8.5,-3.775) 73(8.75,3.775) 74(9,-3.775) 75(9.25,3.775)
CON_2X4_SKT_100_SM
  rect 2.235x1.016 smd: 1(2.826,3.81) 2(-2.826,3.81) 3(2.826,1.27) 4(-2.826,1.27) 5(2.826,-1.27) 6(-2.826,-1.27) 7(2.826,-3.81) 8(-2.826,-3.81)
CON_RJ45_10_2LED_TH
  round 0 hole 3.251 unplated: (-11.43,8.89) (0,8.89)
  rect 1.499x1.499 hole 0.889: 1(0,0)
  round 1.499 hole 0.889: 2(-1.27,2.54) 3(-2.54,0) 4(-3.81,2.54) 5(-5.08,0) 6(-6.35,2.54) 7(-7.62,0) 8(-8.89,2.54) 9(-10.16,0) 10(-11.43,2.54)
  round 1.651 hole 1.016: 11(0.915,12.97) 12(-1.625,12.97) 13(-9.805,12.97) 14(-12.345,12.97)
  round 2.642 hole 1.6: SH1(2.03,5.84) SH2(-13.46,5.84)
DFN2020_0P5_SQ2
  rect 0.483x0.279 smd: 1(-0.91,0.75) 2(-0.91,0.25) 3(-0.91,-0.25) 4(-0.91,-0.75) 5(0.91,-0.75) 6(0.91,-0.25)
  custom 0.12x0.12 smd: 7(0.91,0.75)
  rect 0.914x1.6 smd: 8(0,0)
DIODE2_SOD523
  rect 0.61x0.813 smd: 1(-0.85,0) 2(0.85,0)
DSN0603-2
  rect 0.152x0.254 smd: 1(-0.2,0) 2(0.2,0)
FBGA153_0P5_11P5X13
  round 0.254 smd: A1(-3.25,3.25) A2(-2.75,3.25) A3(-2.25,3.25) A4(-1.75,3.25) A5(-1.25,3.25) A6(-0.75,3.25) A7(-0.25,3.25) A8(0.25,3.25) A9(0.75,3.25) A10(1.25,3.25) A11(1.75,3.25) A12(2.25,3.25) A13(2.75,3.25) A14(3.25,3.25) B1(-3.25,2.75) B2(-2.75,2.75) B3(-2.25,2.75) B4(-1.75,2.75) B5(-1.25,2.75) B6(-0.75,2.75) B7(-0.25,2.75) B8(0.25,2.75) B9(0.75,2.75) B10(1.25,2.75) B11(1.75,2.75) B12(2.25,2.75) B13(2.75,2.75) B14(3.25,2.75) C1(-3.25,2.25) C2(-2.75,2.25) C3(-2.25,2.25) C4(-1.75,2.25) C5(-1.25,2.25) C6(-0.75,2.25) C7(-0.25,2.25) C8(0.25,2.25) C9(0.75,2.25) C10(1.25,2.25) C11(1.75,2.25) C12(2.25,2.25) C13(2.75,2.25) C14(3.25,2.25) D1(-3.25,1.75) D2(-2.75,1.75) D3(-2.25,1.75) D4(-1.75,1.75) D12(2.25,1.75) D13(2.75,1.75) D14(3.25,1.75) E1(-3.25,1.25) E2(-2.75,1.25) E3(-2.25,1.25) E5(-1.25,1.25) E6(-0.75,1.25) E7(-0.25,1.25) E8(0.25,1.25) E9(0.75,1.25) E10(1.25,1.25) E12(2.25,1.25) E13(2.75,1.25) E14(3.25,1.25) F1(-3.25,0.75) F2(-2.75,0.75) F3(-2.25,0.75) F5(-1.25,0.75) F10(1.25,0.75) F12(2.25,0.75) F13(2.75,0.75) F14(3.25,0.75) G1(-3.25,0.25) G2(-2.75,0.25) G3(-2.25,0.25) G5(-1.25,0.25) G10(1.25,0.25) G12(2.25,0.25) G13(2.75,0.25) G14(3.25,0.25) H1(-3.25,-0.25) H2(-2.75,-0.25) H3(-2.25,-0.25) H5(-1.25,-0.25) H10(1.25,-0.25) H12(2.25,-0.25) H13(2.75,-0.25) H14(3.25,-0.25) J1(-3.25,-0.75) J2(-2.75,-0.75) J3(-2.25,-0.75) J5(-1.25,-0.75) J10(1.25,-0.75) J12(2.25,-0.75) J13(2.75,-0.75) J14(3.25,-0.75) K1(-3.25,-1.25) K2(-2.75,-1.25) K3(-2.25,-1.25) K5(-1.25,-1.25) K6(-0.75,-1.25) K7(-0.25,-1.25) K8(0.25,-1.25) K9(0.75,-1.25) K10(1.25,-1.25) K12(2.25,-1.25) K13(2.75,-1.25) K14(3.25,-1.25) L1(-3.25,-1.75) L2(-2.75,-1.75) L3(-2.25,-1.75) L12(2.25,-1.75) L13(2.75,-1.75) L14(3.25,-1.75) M1(-3.25,-2.25) M2(-2.75,-2.25) M3(-2.25,-2.25) M4(-1.75,-2.25) M5(-1.25,-2.25) M6(-0.75,-2.25) M7(-0.25,-2.25) M8(0.25,-2.25) M9(0.75,-2.25) M10(1.25,-2.25) M11(1.75,-2.25) M12(2.25,-2.25) M13(2.75,-2.25) M14(3.25,-2.25) N1(-3.25,-2.75) N2(-2.75,-2.75) N3(-2.25,-2.75) N4(-1.75,-2.75) N5(-1.25,-2.75) N6(-0.75,-2.75) N7(-0.25,-2.75) N8(0.25,-2.75) N9(0.75,-2.75) N10(1.25,-2.75) N11(1.75,-2.75) N12(2.25,-2.75) N13(2.75,-2.75) N14(3.25,-2.75) P1(-3.25,-3.25) P2(-2.75,-3.25) P3(-2.25,-3.25) P4(-1.75,-3.25) P5(-1.25,-3.25) P6(-0.75,-3.25) P7(-0.25,-3.25) P8(0.25,-3.25) P9(0.75,-3.25) P10(1.25,-3.25) P11(1.75,-3.25) P12(2.25,-3.25) P13(2.75,-3.25) P14(3.25,-3.25)
FUSE_3P4X1P8
  rect 0.991x1.803 smd: 1(-1.25,0) 2(1.25,0)
HDR203_TMM_210H
  rect 1.499x1.499 hole 0.889: 1(0,0)
  round 1.499 hole 0.889: 2(0,2) 3(2,0) 4(2,2) 5(4,0) 6(4,2)
HDR204_TMM_SM
  rect 3.302x1.016 smd: 1(-2.134,3.023) 2(2.134,3.023) 3(-2.134,1.016) 4(2.134,1.016) 5(-2.134,-1.016) 6(2.134,-1.016) 7(-2.134,-3.023) 8(2.134,-3.023)
HDR205_10M_50_SM_K
  rect 0.737x2.794 smd: 1(-2.54,-2.032) 2(-2.54,2.032) 3(-1.27,-2.032) 4(-1.27,2.032) 5(0,-2.032) 6(0,2.032) 7(1.27,-2.032) 8(1.27,2.032) 9(2.54,-2.032) 10(2.54,2.032)
HDR220_TSM_A_SM
  round 0 hole 1.727 unplated: (0,22.86) (0,-22.86)
  custom 0.318x0.318 smd: 1(-2.475,24.13) 2(2.475,24.13) 3(-2.475,21.59) 4(2.475,21.59) 37(-2.475,-21.59) 38(2.475,-21.59) 39(-2.475,-24.13) 40(2.475,-24.13)
  rect 3.683x1.27 smd: 5(-2.475,19.05) 6(2.475,19.05) 7(-2.475,16.51) 8(2.475,16.51) 9(-2.475,13.97) 10(2.475,13.97) 11(-2.475,11.43) 12(2.475,11.43) 13(-2.475,8.89) 14(2.475,8.89) 15(-2.475,6.35) 16(2.475,6.35) 17(-2.475,3.81) 18(2.475,3.81) 19(-2.475,1.27) 20(2.475,1.27) 21(-2.475,-1.27) 22(2.475,-1.27) 23(-2.475,-3.81) 24(2.475,-3.81) 25(-2.475,-6.35) 26(2.475,-6.35) 27(-2.475,-8.89) 28(2.475,-8.89) 29(-2.475,-11.43) 30(2.475,-11.43) 31(-2.475,-13.97) 32(2.475,-13.97) 33(-2.475,-16.51) 34(2.475,-16.51) 35(-2.475,-19.05) 36(2.475,-19.05)
HWSON8_0P5_3P1X2P1
  rect 0.635x0.254 smd: 1(-1.412,0.75) 2(-1.412,0.25) 3(-1.412,-0.25) 4(-1.412,-0.75) 5(1.412,-0.75) 6(1.412,-0.25) 7(1.412,0.25) 8(1.412,0.75)
  rect 1.6x1.6 smd: 9(0,0)
HX2QFN16_0P4_2P7X2P7
  rect 0.813x0.203 smd: 1(-1.25,0.8) 2(-1.25,0.4) 3(-1.25,0) 4(-1.25,-0.4) 5(-1.25,-0.8) 9(1.25,-0.8) 10(1.25,-0.4) 11(1.25,0) 12(1.25,0.4) 13(1.25,0.8)
  rect 0.203x0.813 smd: 6(-0.4,-1.25) 7(0,-1.25) 8(0.4,-1.25) 14(0.4,1.25) 15(0,1.25) 16(-0.4,1.25)
  rect 1.194x1.092 smd: 17(0,0)
IND2_7P3X6P8_SM
  rect 2.362x3.505 smd: 1(-3.025,0) 2(3.025,0)
IND4_AMCW3225_SMT
  rect 1.041x1.041 smd: 1(-1.525,-0.725) 2(1.525,-0.725) 3(1.525,0.725) 4(-1.525,0.725)
IND_0603
  rect 0.991x0.813 smd: 1(-0.69,0) 2(0.69,0)
IND_2016A
  rect 0.864x1.803 smd: 1(-0.835,0) 2(0.835,0)
IND_DLW43
  rect 0.914x0.914 smd: 1(-2,1.25) 2(2,1.25) 3(2,-1.25) 4(-2,-1.25)
IND_SPH2520
  rect 1.219x2.007 smd: 1(-1.01,0) 2(1.01,0)
LED4_3P4X3_SM
  rect 0.991x1.803 smd: 1(0.75,1.7) 2(0.75,-1.7) 3(-0.75,-1.7) 4(-0.75,1.7)
LED_0603
  rect 0.838x0.787 smd: A(-0.775,0) C(0.775,0)
LED_0603_11MIL
  rect 0.838x0.787 smd: A(-0.775,0) C(0.775,0)
LGA8_3P1X4P1MM_SPK0641
  rect 0.508x1.016 smd: 1(-0.425,-0.675) 2(-0.425,0.675) 3(0.425,0.675) 4(0.425,-0.675)
  rect 1.321x0.406 smd: 5(0,-1.75) 7(0,1.75)
  rect 0.406x2.311 smd: 6(-1.25,0) 8(1.25,0)
LQFP64_0P5_10X10
  rect 1.372x0.279 smd: 1(-5.775,3.75) 2(-5.775,3.25) 3(-5.775,2.75) 4(-5.775,2.25) 5(-5.775,1.75) 6(-5.775,1.25) 7(-5.775,0.75) 8(-5.775,0.25) 9(-5.775,-0.25) 10(-5.775,-0.75) 11(-5.775,-1.25) 12(-5.775,-1.75) 13(-5.775,-2.25) 14(-5.775,-2.75) 15(-5.775,-3.25) 16(-5.775,-3.75) 33(5.775,-3.75) 34(5.775,-3.25) 35(5.775,-2.75) 36(5.775,-2.25) 37(5.775,-1.75) 38(5.775,-1.25) 39(5.775,-0.75) 40(5.775,-0.25) 41(5.775,0.25) 42(5.775,0.75) 43(5.775,1.25) 44(5.775,1.75) 45(5.775,2.25) 46(5.775,2.75) 47(5.775,3.25) 48(5.775,3.75)
  rect 0.279x1.372 smd: 17(-3.75,-5.775) 18(-3.25,-5.775) 19(-2.75,-5.775) 20(-2.25,-5.775) 21(-1.75,-5.775) 22(-1.25,-5.775) 23(-0.75,-5.775) 24(-0.25,-5.775) 25(0.25,-5.775) 26(0.75,-5.775) 27(1.25,-5.775) 28(1.75,-5.775) 29(2.25,-5.775) 30(2.75,-5.775) 31(3.25,-5.775) 32(3.75,-5.775) 49(3.75,5.775) 50(3.25,5.775) 51(2.75,5.775) 52(2.25,5.775) 53(1.75,5.775) 54(1.25,5.775) 55(0.75,5.775) 56(0.25,5.775) 57(-0.25,5.775) 58(-0.75,5.775) 59(-1.25,5.775) 60(-1.75,5.775) 61(-2.25,5.775) 62(-2.75,5.775) 63(-3.25,5.775) 64(-3.75,5.775)
MH142P080
  round 3.607 hole 2.032: 1(0,0)
MH244-166T_202H
  round 6.198 hole 4.216: 1(0,0)
PBGA208_0P5_9X9MM_SM
  round 0.254 smd: A1(-4,4) A2(-3.5,4) A3(-3,4) A4(-2.5,4) A5(-2,4) A6(-1.5,4) A7(-1,4) A8(-0.5,4) A9(0,4) A10(0.5,4) A11(1,4) A12(1.5,4) A13(2,4) A14(2.5,4) A15(3,4) A16(3.5,4) A17(4,4) B1(-4,3.5) B2(-3.5,3.5) B3(-3,3.5) B4(-2.5,3.5) B5(-2,3.5) B6(-1.5,3.5) B7(-1,3.5) B8(-0.5,3.5) B9(0,3.5) B10(0.5,3.5) B11(1,3.5) B12(1.5,3.5) B13(2,3.5) B14(2.5,3.5) B15(3,3.5) B16(3.5,3.5) B17(4,3.5) C1(-4,3) C2(-3.5,3) C4(-2.5,3) C6(-1.5,3) C8(-0.5,3) C9(0,3) C10(0.5,3) C12(1.5,3) C14(2.5,3) C16(3.5,3) C17(4,3) D1(-4,2.5) D2(-3.5,2.5) D3(-3,2.5) D4(-2.5,2.5) D6(-1.5,2.5) D8(-0.5,2.5) D10(0.5,2.5) D12(1.5,2.5) D14(2.5,2.5) D15(3,2.5) D16(3.5,2.5) D17(4,2.5) E1(-4,2) E2(-3.5,2) E6(-1.5,2) E8(-0.5,2) E10(0.5,2) E12(1.5,2) E16(3.5,2) E17(4,2) F1(-4,1.5) F2(-3.5,1.5) F3(-3,1.5) F4(-2.5,1.5) F5(-2,1.5) F6(-1.5,1.5) F8(-0.5,1.5) F10(0.5,1.5) F12(1.5,1.5) F13(2,1.5) F14(2.5,1.5) F15(3,1.5) F16(3.5,1.5) F17(4,1.5) G1(-4,1) G2(-3.5,1) G6(-1.5,1) G7(-1,1) G9(0,1) G11(1,1) G12(1.5,1) G16(3.5,1) G17(4,1) H1(-4,0.5) H2(-3.5,0.5) H3(-3,0.5) H4(-2.5,0.5) H5(-2,0.5) H7(-1,0.5) H9(0,0.5) H11(1,0.5) H13(2,0.5) H14(2.5,0.5) H15(3,0.5) H16(3.5,0.5) H17(4,0.5) J1(-4,0) J2(-3.5,0) J6(-1.5,0) J12(1.5,0) J16(3.5,0) J17(4,0) K1(-4,-0.5) K2(-3.5,-0.5) K3(-3,-0.5) K4(-2.5,-0.5) K5(-2,-0.5) K7(-1,-0.5) K9(0,-0.5) K11(1,-0.5) K13(2,-0.5) K14(2.5,-0.5) K15(3,-0.5) K16(3.5,-0.5) K17(4,-0.5) L1(-4,-1) L2(-3.5,-1) L6(-1.5,-1) L7(-1,-1) L9(0,-1) L11(1,-1) L12(1.5,-1) L16(3.5,-1) L17(4,-1) M1(-4,-1.5) M2(-3.5,-1.5) M3(-3,-1.5) M4(-2.5,-1.5) M5(-2,-1.5) M6(-1.5,-1.5) M8(-0.5,-1.5) M10(0.5,-1.5) M12(1.5,-1.5) M13(2,-1.5) M14(2.5,-1.5) M15(3,-1.5) M16(3.5,-1.5) M17(4,-1.5) N1(-4,-2) N2(-3.5,-2) N6(-1.5,-2) N8(-0.5,-2) N10(0.5,-2) N12(1.5,-2) N16(3.5,-2) N17(4,-2) P1(-4,-2.5) P2(-3.5,-2.5) P3(-3,-2.5) P4(-2.5,-2.5) P6(-1.5,-2.5) P8(-0.5,-2.5) P10(0.5,-2.5) P12(1.5,-2.5) P14(2.5,-2.5) P15(3,-2.5) P16(3.5,-2.5) P17(4,-2.5) R1(-4,-3) R2(-3.5,-3) R4(-2.5,-3) R6(-1.5,-3) R8(-0.5,-3) R9(0,-3) R10(0.5,-3) R12(1.5,-3) R14(2.5,-3) R16(3.5,-3) R17(4,-3) T1(-4,-3.5) T2(-3.5,-3.5) T3(-3,-3.5) T4(-2.5,-3.5) T5(-2,-3.5) T6(-1.5,-3.5) T7(-1,-3.5) T8(-0.5,-3.5) T9(0,-3.5) T10(0.5,-3.5) T11(1,-3.5) T12(1.5,-3.5) T13(2,-3.5) T14(2.5,-3.5) T15(3,-3.5) T16(3.5,-3.5) T17(4,-3.5) U1(-4,-4) U2(-3.5,-4) U3(-3,-4) U4(-2.5,-4) U5(-2,-4) U6(-1.5,-4) U7(-1,-4) U8(-0.5,-4) U9(0,-4) U10(0.5,-4) U11(1,-4) U12(1.5,-4) U13(2,-4) U14(2.5,-4) U15(3,-4) U16(3.5,-4) U17(4,-4)
PQFN16_0P4_2P65X1P85
  rect 0.203x0.762 smd: 1(-0.6,-0.724)
  rect 0.203x0.66 smd: 2(-0.2,-0.775) 3(0.2,-0.775) 4(0.6,-0.775) 9(0.6,0.775) 10(0.2,0.775) 11(-0.2,0.775) 12(-0.6,0.775)
  rect 0.66x0.203 smd: 5(1.21,-0.6) 6(1.21,-0.2) 7(1.21,0.2) 8(1.21,0.6) 13(-1.21,0.6) 14(-1.21,0.2) 15(-1.21,-0.2) 16(-1.21,-0.6)
QFN12_0P5_2X3MM_EP
  rect 0.711x0.254 smd: 1(-0.95,0.5) 2(-0.95,0) 3(-0.95,-0.5) 7(0.95,-0.5) 8(0.95,0) 9(0.95,0.5)
  rect 0.254x0.914 smd: 4(-0.5,-1.35) 5(0,-1.35) 6(0.5,-1.35)
  custom 0.225x0.225 smd: 10(0,1.35)
  rect 0.406x0.254 smd: 11(0,0)
QFN16_0P65_4X4_A
  rect 0.787x0.356 smd: 1(-1.975,0.975) 2(-1.975,0.325) 3(-1.975,-0.325) 4(-1.975,-0.975) 9(1.975,-0.975) 10(1.975,-0.325) 11(1.975,0.325) 12(1.975,0.975)
  rect 0.356x0.787 smd: 5(-0.975,-1.975) 6(-0.325,-1.975) 7(0.325,-1.975) 8(0.975,-1.975) 13(0.975,1.975) 14(0.325,1.975) 15(-0.325,1.975) 16(-0.975,1.975)
  rect 2.692x2.692 smd: 17(0,0)
QFN24_4X4_EP2P25MM
  oval 0.279x0.813 smd: 1(-1.25,-1.956) 2(-0.75,-1.956) 3(-0.25,-1.956) 4(0.25,-1.956) 5(0.75,-1.956) 6(1.25,-1.956) 13(1.25,1.956) 14(0.75,1.956) 15(0.25,1.956) 16(-0.25,1.956) 17(-0.75,1.956) 18(-1.25,1.956)
  oval 0.813x0.279 smd: 7(1.956,-1.25) 8(1.956,-0.75) 9(1.956,-0.25) 10(1.956,0.25) 11(1.956,0.75) 12(1.956,1.25) 19(-1.956,1.25) 20(-1.956,0.75) 21(-1.956,0.25) 22(-1.956,-0.25) 23(-1.956,-0.75) 24(-1.956,-1.25)
  rect 2.235x2.235 smd: 25(0,0)
QFN40_0P4_5X5_EP146X146
  rect 0.279x0.279 smd: (-2.24,2.24) (-2.24,-2.24) (2.24,2.24) (2.24,-2.24)
  oval 0.838x0.203 smd: 1(-2.487,1.8) 2(-2.487,1.4) 3(-2.487,1) 4(-2.487,0.6) 5(-2.487,0.2) 6(-2.487,-0.2) 7(-2.487,-0.6) 8(-2.487,-1) 9(-2.487,-1.4) 10(-2.487,-1.8)
  oval 0.203x0.864 smd: 11(-1.8,-2.475) 12(-1.4,-2.475) 13(-1,-2.475) 14(-0.6,-2.475) 15(-0.2,-2.475) 16(0.2,-2.475) 17(0.6,-2.475) 18(1,-2.475) 19(1.4,-2.475) 20(1.8,-2.475) 31(1.8,2.475) 32(1.4,2.475) 33(1,2.475) 34(0.6,2.475) 35(0.2,2.475) 36(-0.2,2.475) 37(-0.6,2.475) 38(-1,2.475) 39(-1.4,2.475) 40(-1.8,2.475)
  oval 0.864x0.203 smd: 21(2.487,-1.8) 22(2.487,-1.4) 23(2.487,-1) 24(2.487,-0.6) 25(2.487,-0.2) 26(2.487,0.2) 27(2.487,0.6) 28(2.487,1) 29(2.487,1.4) 30(2.487,1.8)
  rect 3.607x3.607 smd: 41(0,0)
QFN40_0P4_5X5MM
  oval 0.813x0.203 smd: 1(-2.46,1.8) 10(-2.46,-1.8) 21(2.46,-1.8) 30(2.46,1.8)
  rect 0.813x0.203 smd: 2(-2.46,1.4) 3(-2.46,1) 4(-2.46,0.6) 5(-2.46,0.2) 6(-2.46,-0.2) 7(-2.46,-0.6) 8(-2.46,-1) 9(-2.46,-1.4) 22(2.46,-1.4) 23(2.46,-1) 24(2.46,-0.6) 25(2.46,-0.2) 26(2.46,0.2) 27(2.46,0.6) 28(2.46,1) 29(2.46,1.4)
  oval 0.203x0.813 smd: 11(-1.8,-2.46) 20(1.8,-2.46) 31(1.8,2.46) 40(-1.8,2.46)
  rect 0.203x0.813 smd: 12(-1.4,-2.46) 13(-1,-2.46) 14(-0.6,-2.46) 15(-0.2,-2.46) 16(0.2,-2.46) 17(0.6,-2.46) 18(1,-2.46) 19(1.4,-2.46) 32(1.4,2.46) 33(1,2.46) 34(0.6,2.46) 35(0.2,2.46) 36(-0.2,2.46) 37(-0.6,2.46) 38(-1,2.46) 39(-1.4,2.46)
  rect 3.607x3.607 smd: 41(0,0)
QFN0505-32B_0P5
  rect 0.508x0.508 smd: (-2.45,2.45) (-2.45,-2.45) (2.45,2.45) (2.45,-2.45)
  rect 0.508x0.254 smd: 1(-2.45,1.75) 2(-2.45,1.25) 3(-2.45,0.75) 4(-2.45,0.25) 5(-2.45,-0.25) 6(-2.45,-0.75) 7(-2.45,-1.25) 8(-2.45,-1.75) 17(2.45,-1.75) 18(2.45,-1.25) 19(2.45,-0.75) 20(2.45,-0.25) 21(2.45,0.25) 22(2.45,0.75) 23(2.45,1.25) 24(2.45,1.75)
  rect 0.254x0.508 smd: 9(-1.75,-2.45) 10(-1.25,-2.45) 11(-0.75,-2.45) 12(-0.25,-2.45) 13(0.25,-2.45) 14(0.75,-2.45) 15(1.25,-2.45) 16(1.75,-2.45) 25(1.75,2.45) 26(1.25,2.45) 27(0.75,2.45) 28(0.25,2.45) 29(-0.25,2.45) 30(-0.75,2.45) 31(-1.25,2.45) 32(-1.75,2.45)
  rect 2.235x1.448 smd: 33(0.25,1.225)
  rect 1.753x2.21 smd: 34(-1.075,-0.85)
  rect 1.5x2.2 smd: 35(1.2,-0.85)
RC0402_25
  round 0.635 smd: 1(-0.508,0) 2(0.508,0)
RC0603_OV
  oval 0.889x1.143 smd: 1(-0.762,0) 2(0.762,0)
RC0805_OV
  oval 0.889x1.524 smd: 1(-0.965,0) 2(0.965,0)
SC70-5
  rect 0.406x0.813 smd: 1(-0.65,-1.079) 2(0,-1.079) 3(0.65,-1.079) 4(0.65,1.079) 5(-0.65,1.079)
SC70_3
  rect 0.711x0.889 smd: 1(-0.648,-0.952) 2(0.648,-0.952) 3(0,0.952)
SO8_1P27_4X5
  rect 1.6x0.61 smd: 1(-2.7,1.905) 2(-2.7,0.635) 3(-2.7,-0.635) 4(-2.7,-1.905) 5(2.7,-1.905) 6(2.7,-0.635) 7(2.7,0.635) 8(2.7,1.905)
SO16_0P5_3P5X4P5_MM
  rect 0.889x0.279 smd: 1(-1.7,1.75) 2(-1.7,1.25) 3(-1.7,0.75) 4(-1.7,0.25) 5(-1.7,-0.25) 6(-1.7,-0.75) 7(-1.7,-1.25) 8(-1.7,-1.75) 9(1.7,-1.75) 10(1.7,-1.25) 11(1.7,-0.75) 12(1.7,-0.25) 13(1.7,0.25) 14(1.7,0.75) 15(1.7,1.25) 16(1.7,1.75)
  rect 2x3.8 smd: 17(0,0)
SOD323
  rect 0.889x1.219 smd: A(0,1.27) C(0,-1.27)
SOD523
  rect 0.61x0.813 smd: A(0.85,0) C(-0.85,0)
SOT23-5
  rect 0.61x1.118 smd: 1(-0.95,-1.425) 2(0,-1.425) 3(0.95,-1.425) 4(0.95,1.425) 5(-0.95,1.425)
SOT23-6
  rect 0.61x1.118 smd: 1(-0.95,-1.321) 2(0,-1.321) 3(0.95,-1.321) 4(0.95,1.321) 5(0,1.321) 6(-0.95,1.321)
SOT23_A
  rect 0.787x0.889 smd: 1(-0.94,-1.003) 2(0.94,-1.003) 3(0,1.003)
SOT753_5P_1P7X3P1MM
  rect 1.321x0.406 smd: 1(-1.175,0.95) 2(-1.175,0) 3(-1.175,-0.95) 4(1.175,-0.95) 5(1.175,0.95)
SOT-23
  rect 1.016x1.397 smd: 1(-0.95,-1.1) 2(0.95,-1.1) 3(0,1.1)
SOT-23-5
  rect 0.686x0.991 smd: 1(-0.953,-1.295) 2(0,-1.295) 3(0.953,-1.295) 4(0.953,1.295) 5(-0.953,1.295)
SSOP8_DCU
  rect 0.279x1.219 smd: 1(-0.75,-1.499) 2(-0.25,-1.499) 3(0.25,-1.499) 4(0.75,-1.499) 5(0.75,1.499) 6(0.25,1.499) 7(-0.25,1.499) 8(-0.75,1.499)
SW4_SKRP
  rect 1.499x0.762 smd: 1(-2.3,1.075) 2(2.3,1.075) 3(-2.3,-1.075) 4(2.3,-1.075)
SW6_DPDT_M096H_TH
  rect 1.346x1.346 hole 0.711: 1(0,0)
  round 1.346 hole 0.711: 2(0,-2.5) 3(0,-5) 4(3.2,0) 5(3.2,-2.5) 6(3.2,-5)
SW_2P8X5P7_SM
  rect 1.016x1.6 smd: 1(0,2.54) 2(0,-2.54)
SW_CHS_04_A
  rect 1.6x0.762 smd: 1(-2.54,1.905) 2(2.54,1.905) 3(-2.54,0.635) 4(2.54,0.635) 5(-2.54,-0.635) 6(2.54,-0.635) 7(-2.54,-1.905) 8(2.54,-1.905)
TEST_PIN_TP107
  rect 4.699x3.429 smd: 1(0,0)
TESTPOINT_35MIL
  round 0.889 smd: 1(0,0)
TPAD_015
  round 0.381 smd: 1(0,0)
TPAD_020
  round 0.508 smd: 1(0,0)
TPAD_050
  round 1.27 smd: 1(0,0)
TSSOP16
  rect 1.524x0.305 smd: 1(-3.048,2.276) 2(-3.048,1.626) 3(-3.048,0.975) 4(-3.048,0.325) 5(-3.048,-0.325) 6(-3.048,-0.975) 7(-3.048,-1.626) 8(-3.048,-2.276) 9(3.048,-2.276) 10(3.048,-1.626) 11(3.048,-0.975) 12(3.048,-0.325) 13(3.048,0.325) 14(3.048,0.975) 15(3.048,1.626) 16(3.048,2.276)
UDFN6_1X1P5MM
  rect 0.584x0.305 smd: 1(-0.418,0.5)
  rect 0.508x0.305 smd: 2(-0.38,0) 3(-0.38,-0.5) 4(0.38,-0.5) 5(0.38,0) 6(0.38,0.5)
unnamed#2
  round 1.016 smd: (0,0)
unnamed#3
  round 0 hole 1.702 unplated: (-6.362,6.363) (-6.362,-6.363) (6.362,6.363) (6.362,-6.363)
  round 0 hole 0.848 unplated: (-6.362,-1.282) (6.362,3.822)
UQFN12_1P7X2MM
  rect 0.686x0.305 smd: 1(-0.655,0.84)
  rect 0.69x0.22 smd: 2(-0.655,0.4) 3(-0.655,0) 4(-0.655,-0.4) 5(-0.655,-0.8) 7(0.655,-0.8) 8(0.655,-0.4) 9(0.655,0) 10(0.655,0.4) 11(0.655,0.8)
  rect 0.22x0.69 smd: 6(0,-0.805) 12(0,0.805)
UQFN32_0P5_5X5_EP3X3
  rect 0.914x0.279 smd: 1(-2.55,1.75) 2(-2.55,1.25) 3(-2.55,0.75) 4(-2.55,0.25) 5(-2.55,-0.25) 6(-2.55,-0.75) 7(-2.55,-1.25) 8(-2.55,-1.75) 17(2.55,-1.75) 18(2.55,-1.25) 19(2.55,-0.75) 20(2.55,-0.25) 21(2.55,0.25) 22(2.55,0.75) 23(2.55,1.25) 24(2.55,1.75)
  rect 0.279x0.914 smd: 9(-1.75,-2.55) 10(-1.25,-2.55) 11(-0.75,-2.55) 12(-0.25,-2.55) 13(0.25,-2.55) 14(0.75,-2.55) 15(1.25,-2.55) 16(1.75,-2.55) 25(1.75,2.55) 26(1.25,2.55) 27(0.75,2.55) 28(0.25,2.55) 29(-0.25,2.55) 30(-0.75,2.55) 31(-1.25,2.55) 32(-1.75,2.55)
  rect 2.997x2.997 smd: 33(0,0)
USB6P_TYPEC_RA_SM
  round 0 hole 0.95 unplated: (-3.25,1.275) (3.25,1.275)
  rect 0.711x1.397 smd: A5(-0.5,3.245) B5(0.5,3.245)
  rect 0.762x1.397 smd: A9(1.52,3.245) B9(-1.52,3.245)
  rect 0.813x1.397 smd: A12(2.75,3.245) B12(-2.75,3.245)
  oval 0.889x1.575 hole 0.508x1.194: SH1(-4.895,1.275) SH2(4.895,1.275) SH3(-4.895,-1.725) SH4(4.895,-1.725)
WLCSP4_0P5_0P99X0P99
  round 0.254 smd: A1(-0.25,0.25) A2(0.25,0.25) B1(-0.25,-0.25) B2(0.25,-0.25)
WLCSP5_0P4_0P82X1P22
  round 0.254 smd: A1(-0.2,0.4) A2(0.2,0.4) B1(0,0) C1(-0.2,-0.4) C2(0.2,-0.4)
WLCSP6_0P4_0P84X1P18
  round 0.24 smd: A1(-0.2,0.4) A2(0.2,0.4) B1(-0.2,0) B2(0.2,0) C1(-0.2,-0.4) C2(0.2,-0.4)
WLCSP6_0P5_0P89X1P39
  round 0.2 smd: A1(-0.25,0.5) A2(0.25,0.5) B1(-0.25,0) B2(0.25,0) C1(-0.25,-0.5) C2(0.25,-0.5)
WLCSP12_0P4_1P3X1P7MM_SMDP
  round 0.254 smd: A1(-0.4,0.6) A2(0,0.6) A3(0.4,0.6) B1(-0.4,0.2) B2(0,0.2) B3(0.4,0.2) C1(-0.4,-0.2) C2(0,-0.2) C3(0.4,-0.2) D1(-0.4,-0.6) D2(0,-0.6) D3(0.4,-0.6)
WLCSP15_0P5_1P57X2P59
  round 0.254 smd: A1(0.5,1) A2(0,1) A3(-0.5,1) B1(0.5,0.5) B2(0,0.5) B3(-0.5,0.5) C1(0.5,0) C2(0,0) C3(-0.5,0) D1(0.5,-0.5) D2(0,-0.5) D3(-0.5,-0.5) E1(0.5,-1) E2(0,-1) E3(-0.5,-1)
WLCSP42_0P4_2P94X2P54_SMDP
  round 0.254 smd: A1(-1,1.2) A2(-0.6,1.2) A3(-0.2,1.2) A4(0.2,1.2) A5(0.6,1.2) A6(1,1.2) B1(-1,0.8) B2(-0.6,0.8) B3(-0.2,0.8) B4(0.2,0.8) B5(0.6,0.8) B6(1,0.8) C1(-1,0.4) C2(-0.6,0.4) C3(-0.2,0.4) C4(0.2,0.4) C5(0.6,0.4) C6(1,0.4) D1(-1,0) D2(-0.6,0) D3(-0.2,0) D4(0.2,0) D5(0.6,0) D6(1,0) E1(-1,-0.4) E2(-0.6,-0.4) E3(-0.2,-0.4) E4(0.2,-0.4) E5(0.6,-0.4) E6(1,-0.4) F1(-1,-0.8) F2(-0.6,-0.8) F3(-0.2,-0.8) F4(0.2,-0.8) F5(0.6,-0.8) F6(1,-0.8) G1(-1,-1.2) G2(-0.6,-1.2) G3(-0.2,-1.2) G4(0.2,-1.2) G5(0.6,-1.2) G6(1,-1.2)
WSON8_1P27_8X6MM_EP136X171
  rect 0.914x0.508 smd: 1(-3.901,1.905) 2(-3.901,0.635) 3(-3.901,-0.635) 4(-3.901,-1.905) 5(3.901,-1.905) 6(3.901,-0.635) 7(3.901,0.635) 8(3.901,1.905)
  rect 3.454x4.343 smd: 9(0,0)
WSON10_0P5_2P1X3P1
  rect 0.457x0.254 smd: 1(-0.975,1) 2(-0.975,0.5) 3(-0.975,0) 4(-0.975,-0.5) 5(-0.975,-1) 6(0.975,-1) 7(0.975,-0.5)
  rect 0.559x1.499 smd: 10(0.975,0.58)
  rect 1.092x2.692 smd: 11(0,0)
XQFN12_0P4_1P8X2P1
  rect 0.66x0.305 smd: 1(-0.675,0.85)
  rect 0.66x0.203 smd: 2(-0.675,0.4) 3(-0.675,0) 4(-0.675,-0.4) 5(-0.675,-0.8) 7(0.675,-0.8) 8(0.675,-0.4) 9(0.675,0) 10(0.675,0.4) 11(0.675,0.8)
  rect 0.203x0.66 smd: 6(0,-0.825) 12(0,0.825)
XQFN16_0P4_2P7X1P9
  rect 0.203x0.965 smd: 1(-0.6,-0.625) 2(-0.2,-0.625) 3(0.2,-0.625) 4(0.6,-0.625) 9(0.6,0.625) 10(0.2,0.625) 11(-0.2,0.625) 12(-0.6,0.625)
  rect 0.66x0.203 smd: 5(1.21,-0.6) 6(1.21,-0.2) 7(1.21,0.2) 8(1.21,0.6) 13(-1.21,0.6) 14(-1.21,0.2) 15(-1.21,-0.2) 16(-1.21,-0.6)
XSON10_0P5_1P1X2P6MM
  rect 0.711x0.254 smd: 1(-0.457,1) 2(-0.457,0.5) 3(-0.457,0) 4(-0.457,-0.5) 5(-0.457,-1) 6(0.457,-1) 7(0.457,-0.5) 8(0.457,0) 9(0.457,0.5) 10(0.457,1)
XTAL2-3P2X1P5-SM
  rect 1.092x1.905 smd: 1(-1.25,0) 2(1.25,0)
XTAL_4_3P3X2P6MM
  rect 1.397x1.194 smd: 1(-1.1,-0.85) 2(1.1,-0.85) 3(1.1,0.85) 4(-1.1,0.85)
XTL4_2P5X2MM_SM
  rect 0.991x0.889 smd: 1(-0.925,-0.775) 2(0.925,-0.775) 3(0.925,0.775) 4(-0.925,0.775)
XTLOSC4_3P2X2P5MM_SM
  rect 1.397x1.194 smd: 1(-1.1,-0.8) 2(1.1,-0.8) 3(1.1,0.8) 4(-1.1,0.8)

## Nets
5V_PG: R323.2 TP151.1(PIN1) U39.1
AGND: C254.1 R439.2 U23.34
